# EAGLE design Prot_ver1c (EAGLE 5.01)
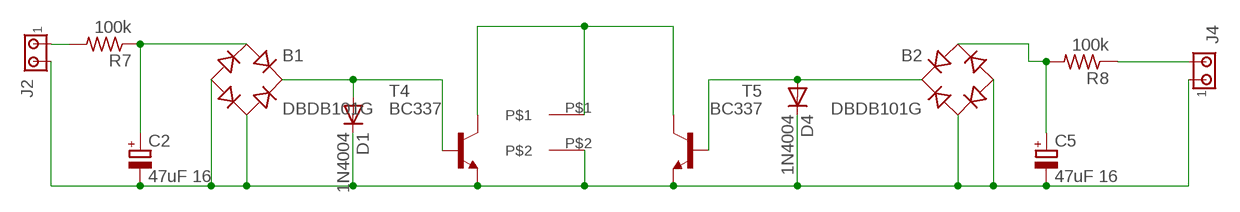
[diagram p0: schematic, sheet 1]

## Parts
B1  DBDB101G  [DB]
B2  DBDB101G  [DB]
C2  47uF 16  CPOL-EUE3.5-10  [E3,5-10]
C5  47uF 16  CPOL-EUE3.5-10  [E3,5-10]
D1  1N4004  [DO41-10]
D4  1N4004  [DO41-10]
J2  MTA02-156  [1X2MTA]
J4  MTA02-156  [1X2MTA]
R7  100k  R-US_0207/12  [0207/12]
R8  100k  R-US_0207/12  [0207/12]
T4  BC337  [TO92]
T5  BC337  [TO92]
U$2  PINS  [PINS]

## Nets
N$1: B1.+ D1.A T4.2(B)
N$4: B2.+ D4.A T5.2(B)
N$6: B2.AC1 C5.+ R8.2
N$7: J4.2 R8.1
N$8: B1.- B1.AC2 B2.- B2.AC2 C2.- C5.- D1.C D4.C J2.2 J4.1 T4.1(E) T5.1(E) U$2.P$2
N$12: J2.1 R7.2
N$13: B1.AC1 C2.+ R7.1
N$15: T4.3(C) T5.3(C) U$2.P$1

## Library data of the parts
B1 B2 = rectifier:DB?*G: Single Phase 1.0 AMP Glass Passivated Bridge Rectifier Taiwan Semiconductor Co.,Ltd. - TSC Source: http://www.taiwansemi.com/TSCbig5/ezcatfiles/cust/img/img/db101g.pdf http://www.ts.com.tw/db/pictures/modules/PDT/PDT060207001/DBLS201G.pdf
C2 C5 = rcl:CPOL-EU: POLARIZED CAPACITOR, European symbol
D1 D4 = diode:1N4004: DIODE
J2 J4 = con-amp:MTA02-156: AMP connector
R7 R8 = rcl:R-US_: RESISTOR, American symbol
T4 T5 = transistor-neu-to92:BC337: NPN TRANSISTOR
U$2 = varie:PINS

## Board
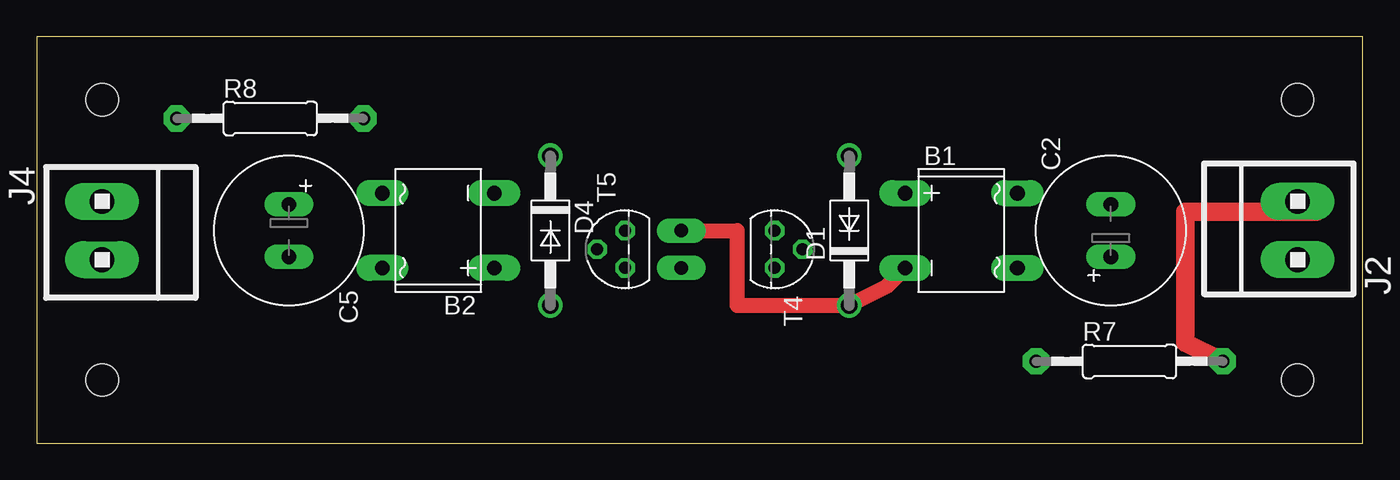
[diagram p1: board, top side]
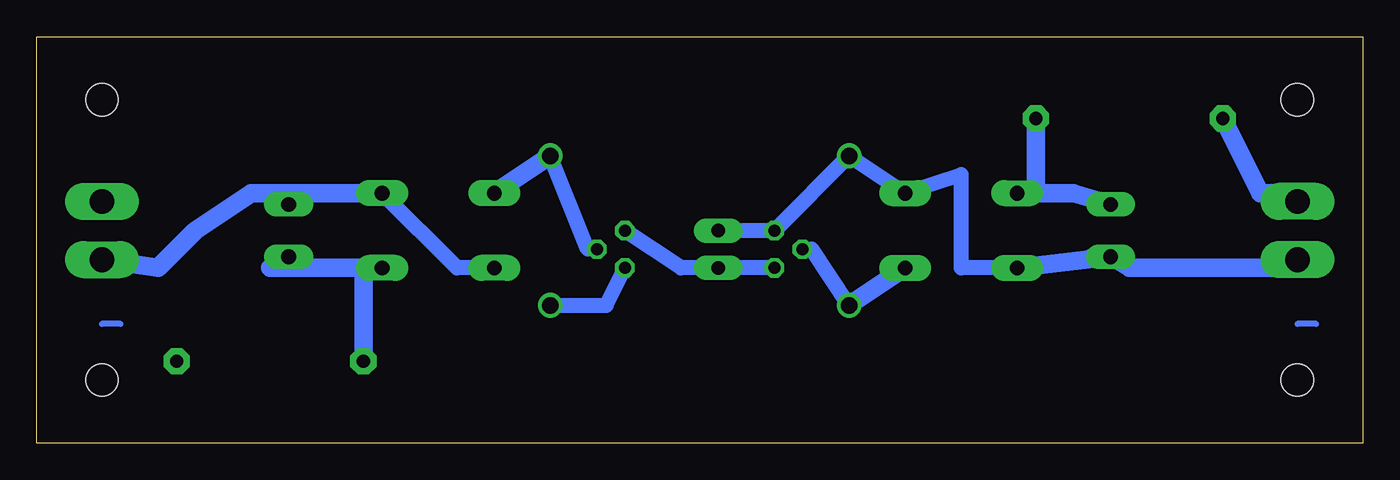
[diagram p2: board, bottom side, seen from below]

Size 90.15 x 27.61 mm. Coordinates in mm from the lower left corner, seen from the top.
Outline: 0,0 90.15,0 90.15,27.61 0,27.61 0,0
Copper layers (1*16): Top 0.035mm / dielectric 1.5mm / Bottom 0.035mm
Design rules "default": minimum track width 10mil, minimum drill 24mil, track to track 8mil, track to pad 8mil, pad to pad 8mil, via to via 8mil, smd to smd 8mil, copper to edge 40mil, drill to drill 8mil, minimum pad ring 10mil, minimum via ring 8mil, stop-mask expansion 4mil, vias tented up to drill 0mil, thermal gap 10mil
Holes 2.2 mm at 4.44,4.28 4.44,23.33 85.72,4.28 85.72,23.33

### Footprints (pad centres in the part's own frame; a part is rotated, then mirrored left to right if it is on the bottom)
DB = drill 1 pad 1.778 long: + -2.54,-3.81; - 2.54,-3.81; AC1 2.54,3.81; AC2 -2.54,3.81
E3,5-10 = drill 1 pad 1.676 long: + -1.778,0; - 1.778,0
DO41-10 = drill 1.118 round: A 5.08,0; C -5.08,0
1X2MTA = drill 1.676 long: 1 1.981,0; 2 -1.981,0
0207/12 = drill 0.9 pad 1.778 octagon: 1 -6.35,0; 2 6.35,0
TO92 = drill 0.813 octagon: 1 1.27,0; 2 0,1.905; 3 -1.27,0
PINS = drill 0.9 pad 1.676 long: P$1 -2.54,0; P$2 0,0

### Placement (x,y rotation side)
B1  62.86,14.44 270 top
B2  27.3,14.44 90 top
C2  73.02,14.44 90 top
C5  17.14,14.44 270 top
D1  55.24,14.44 90 top
D4  34.92,14.44 270 top
J2  85.72,14.44 90 top
J4  4.44,14.44 270 top
R7  74.29,5.55 0 top
R8  15.87,22.06 0 top
T4  50.16,13.17 270 top
T5  40,13.17 90 top
U$2  43.81,14.44 90 top

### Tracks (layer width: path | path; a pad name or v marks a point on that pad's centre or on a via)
N$1
  Bottom 0.254: T4.2 52.7,13.17
  Bottom 1.016: 52.7,13.17 D1.A B1.+
  Bottom 1.27: D1.A B1.+
N$2
  Bottom 0.406: 3.17,8.09 4.44,8.09
N$4
  Bottom 0.254: 37.46,13.17 T5.2
  Bottom 1.016: 37.46,13.17 D4.A B2.+
  Bottom 1.27: B2.+ D4.A
N$5
  Bottom 0.406: 84.45,8.09 85.72,8.09
N$6
  Bottom 1.27: 22.22,16.98 19.68,16.98 C5.+ | 22.22,16.98 B2.AC1 | 22.22,16.98 R8.2
N$7
  Bottom 0.254: J4.2 5.71,16.98
  Bottom 1.27: R8.1 6.98,16.98 5.71,16.98
N$8
  Top 1.016: U$2.P$2 47.62,14.44 47.62,9.36 D1.C 57.78,10.63 B1.-
  Bottom 0.254: 75.56,16.98 C2.- | C5.- 18.41,13.17 20.95,11.9 B2.AC2 | J4.1 5.71,11.9
  Bottom 1.016: B1.AC2 61.59,11.9 B1.- | U$2.P$2 T5.1 D4.C B2.- 27.3,18.25 27.3,11.9 B2.AC2 | T4.1 51.43,9.36 D1.C
  Bottom 1.27: B1.AC2 75.56,16.98 79.37,14.44 81.91,11.9 J2.2 | 5.71,11.9 15.87,11.9 C5.- B2.AC2
N$12
  Top 1.27: R7.2 78.1,6.82 78.1,15.71 86.99,15.71 J2.1
N$13
  Bottom 1.27: 67.94,11.9 74.29,11.9 C2.+ | 67.94,11.9 B1.AC1 | R7.1 67.94,11.9
N$15
  Bottom 1.016: T5.3 U$2.P$1 46.35,11.9 T4.3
